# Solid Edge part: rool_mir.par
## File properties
Author: Argu
Template: Iso Part.par
Last saved by: Argu
Revision: 4
Application: Solid Edge
Accuracy: 0,990
Username: Argu
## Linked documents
rool.par
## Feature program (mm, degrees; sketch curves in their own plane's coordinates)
part copy "CopiedPart_1"
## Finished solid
Body 1: solid body, 20 faces, 32 edges, 14 vertices.
  Faces by surface: torus 6, plane 5, blend 3, cylinder 3, spline 2, sphere 1
  Edges by curve: intersection 17, circle 15
Bounding box of the edges (mm; curved faces can reach further): 9.500 x 66.750 x 9.500, from (-8, -60, -4.75) to (1.5, 6.75, 4.75).
Cylindrical faces by radius (mm): R0.75 x2, R1.5 x1
Toroidal faces (ring radius, tube radius in mm): R0.5 r0.25 x2, R3.5 r0.75 x3, R3.5026 r0.75 x1
Spherical faces by radius (mm): R1.4987 x1
Planar faces by outward normal: +y 2, -x 2, -y 1
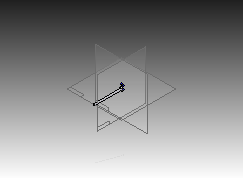
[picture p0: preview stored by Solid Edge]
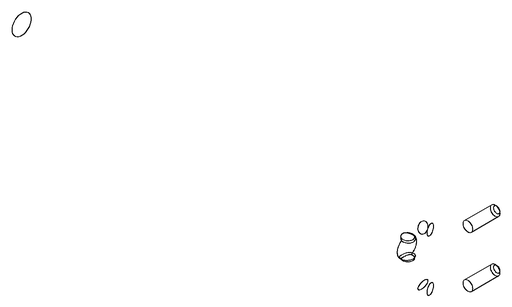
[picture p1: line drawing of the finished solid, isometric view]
